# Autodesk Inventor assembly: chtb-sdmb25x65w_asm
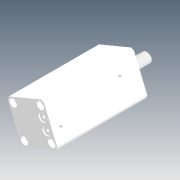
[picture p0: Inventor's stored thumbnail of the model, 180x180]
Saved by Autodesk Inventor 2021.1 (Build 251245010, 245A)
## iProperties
Company: Microsoft
Created: 2018-05
Part Number: chtb-sdmb25x65w_asm
Description: STEP AP214
Document SubType Name: Assembly
Designer: user
Title: chtb-sdmb25x65w_asm.STEP
Author: Windows
Revision Number: ÈÎºÎ
Sending System: SolidWorks 2015
Preprocessor: SwSTEP 2.0
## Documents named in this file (4)
- D:\Vault_2016\Projekty\Clamptek\Hydraulic\CHTB\CHTB-25\Inventor\chtb-sdmb25x65w\chtb-sdmb25x65w_asm.iam
- D:\Vault_2016\Projekty\Clamptek\Hydraulic\CHTB\CHTB-25\Inventor\chtb-sdmb25x65w\CHTB-25QG.ipt
- D:\Vault_2016\Projekty\Clamptek\Hydraulic\CHTB\CHTB-25\Inventor\chtb-sdmb25x65w\CHTB-SDMB25X65NBT.ipt
- D:\Vault_2016\Projekty\Clamptek\Hydraulic\CHTB\CHTB-25\Inventor\chtb-sdmb25x65w\CHTB-SDMB25X65WHSG.ipt
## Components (3 placed, 3 different names)
1. CHTB-25QG_1
2. CHTB-SDMB25X65NBT_2
3. CHTB-SDMB25X65WHSG_3
